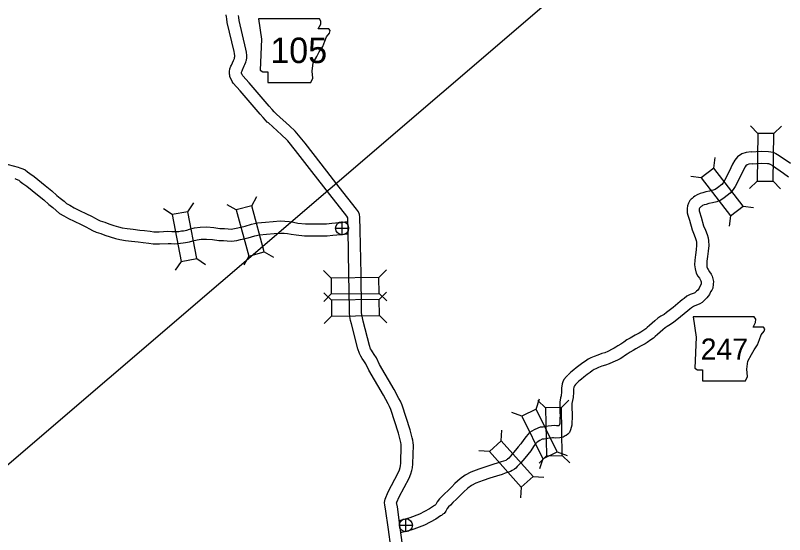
# Model space of a CAD drawing. Extents: x 1374139 to 1377472, y 1168351 to 1170484.
# Drawn here: x 1374736.9 to 1374928.1, y 1170047.2 to 1170176.4 of the extents above; entities that cross this region are included whole.
import ezdxf

# ---------------------------------------------------------------- set-up
doc = ezdxf.new("R2010")
doc.units = 0
doc.layers.add('15', color=7, linetype='Continuous')
doc.layers.add('Default', color=7, linetype='Continuous')

msp = doc.modelspace()

# ---------------------------------------------------------------- linework, layer by layer
at = {"layer": '15'}
msp.add_line((1374910.7, 1170215.21), (1374680.58, 1170017.86), dxfattribs=at)
at = {"layer": 'Default'}
for p, q in [((1374921.48, 1170147.03), (1374919.64, 1170148.92)), ((1374925.44, 1170146.98), (1374927.33, 1170148.82)), ((1374910.54, 1170138.37), (1374910.88, 1170140.99)), ((1374907.4, 1170135.95), (1374904.79, 1170136.3)), ((1374921.32, 1170135.15), (1374919.43, 1170133.31)), ((1374925.28, 1170135.1), (1374927.12, 1170133.2)), ((1374795.65, 1170129.01), (1374796.96, 1170131.3)), ((1374779.81, 1170127.53), (1374781.3, 1170129.71)), ((1374791.83, 1170127.96), (1374789.54, 1170129.27)), ((1374775.92, 1170126.8), (1374773.74, 1170128.29)), ((1374917.79, 1170128.95), (1374920.4, 1170128.61)), ((1374914.65, 1170126.54), (1374914.31, 1170123.92)), ((1374816.51, 1170123.43), (1374819.76, 1170123.43)), ((1374818.13, 1170121.81), (1374818.13, 1170125.06)), ((1374781.99, 1170115.85), (1374784.17, 1170114.36)), ((1374794.97, 1170116.5), (1374793.66, 1170114.21)), ((1374798.79, 1170117.55), (1374801.08, 1170116.24)), ((1374778.1, 1170115.12), (1374776.6, 1170112.95)), ((1374815.4, 1170111.03), (1374813.52, 1170112.88)), ((1374827.28, 1170111.17), (1374829.13, 1170113.06)), ((1374815.47, 1170105.53), (1374813.58, 1170107.37)), ((1374815.45, 1170107.07), (1374813.6, 1170105.18)), ((1374827.33, 1170107.21), (1374829.22, 1170105.36)), ((1374827.35, 1170105.66), (1374829.19, 1170107.55)), ((1374815.51, 1170101.57), (1374813.67, 1170099.68)), ((1374827.39, 1170101.7), (1374829.28, 1170099.86)), ((1374866.36, 1170078.43), (1374867.22, 1170080.93)), ((1374868.71, 1170078.7), (1374866.81, 1170080.53)), ((1374872.67, 1170078.77), (1374874.51, 1170080.67)), ((1374862.8, 1170076.69), (1374860.3, 1170077.55)), ((1374857.67, 1170070.49), (1374857.82, 1170073.13)), ((1374854.73, 1170067.85), (1374852.09, 1170067.99)), ((1374868.92, 1170066.82), (1374867.08, 1170064.92)), ((1374868.02, 1170066.02), (1374867.16, 1170063.52)), ((1374871.58, 1170067.76), (1374874.07, 1170066.9)), ((1374872.87, 1170066.89), (1374874.77, 1170065.05)), ((1374865.6, 1170061.64), (1374868.24, 1170061.5)), ((1374862.66, 1170059), (1374862.51, 1170056.36)), ((1374833.98, 1170047.87), (1374833.98, 1170051.12)), ((1374832.35, 1170049.5), (1374835.6, 1170049.5))]:
    msp.add_line(p, q, dxfattribs=at)
for points in [[(1374789.41, 1170175.95), (1374789.32, 1170176.49)], [(1374830.21, 1170044.11), (1374829.63, 1170048.48), (1374828.9, 1170053.55), (1374828.71, 1170054.49), (1374828.68, 1170055.13), (1374828.8, 1170056.01), (1374829.58, 1170057.85), (1374832.08, 1170062.51), (1374832.4, 1170063.26), (1374832.56, 1170063.84), (1374832.65, 1170064.26), (1374832.72, 1170064.97), (1374832.84, 1170069.37), (1374832.83, 1170069.63), (1374832.75, 1170070.07), (1374832.65, 1170070.47), (1374832.13, 1170072.42), (1374830.22, 1170078.33), (1374829.9, 1170079.08), (1374829.58, 1170079.69), (1374828.42, 1170081.86), (1374824.8, 1170088.07), (1374824.01, 1170089.67), (1374823.56, 1170090.39), (1374823.15, 1170091.02), (1374822.81, 1170091.55), (1374822.45, 1170092.24), (1374822.04, 1170093.38), (1374820.44, 1170099.61), (1374820.23, 1170100.49), (1374820.02, 1170101.48), (1374819.98, 1170102.28), (1374819.93, 1170103.18), (1374819.83, 1170111.98), (1374819.64, 1170122.87), (1374819.56, 1170125.99), (1374819.55, 1170126.04), (1374819.3, 1170126.41), (1374815.06, 1170131.82), (1374810.59, 1170137.58), (1374806.57, 1170142.73), (1374804.63, 1170145.16), (1374804.36, 1170145.46), (1374803.03, 1170146.69), (1374799.81, 1170149.62), (1374799.54, 1170149.85), (1374799.08, 1170150.28), (1374798.51, 1170150.95), (1374797.73, 1170151.82), (1374792.76, 1170157.62), (1374791.08, 1170159.56), (1374790.82, 1170159.96), (1374790.68, 1170160.15), (1374790.39, 1170160.74), (1374790.25, 1170161.18), (1374790.19, 1170161.5), (1374790.15, 1170161.8), (1374790.1, 1170162.43), (1374790.24, 1170163.12), (1374790.48, 1170163.74), (1374790.61, 1170164.04), (1374791.1, 1170165.17), (1374791.26, 1170165.47), (1374791.34, 1170165.66), (1374791.38, 1170165.83), (1374791.4, 1170165.89), (1374791.43, 1170166.12), (1374791.44, 1170166.33), (1374791.38, 1170166.87), (1374791.29, 1170167.42), (1374789.56, 1170174.63), (1374789.46, 1170175.5), (1374789.4, 1170176.02)], [(1374833.17, 1170044.6), (1374832.6, 1170048.89), (1374831.86, 1170054.05), (1374831.7, 1170054.85), (1374831.69, 1170055), (1374831.72, 1170055.22), (1374832.28, 1170056.55), (1374834.79, 1170061.21), (1374835.24, 1170062.27), (1374835.47, 1170063.12), (1374835.62, 1170063.78), (1374835.72, 1170064.78), (1374835.85, 1170069.43), (1374835.81, 1170069.99), (1374835.69, 1170070.69), (1374835.55, 1170071.22), (1374835.01, 1170073.26), (1374833.03, 1170079.39), (1374832.61, 1170080.37), (1374832.23, 1170081.09), (1374831.04, 1170083.32), (1374827.44, 1170089.49), (1374826.64, 1170091.13), (1374826.08, 1170092.01), (1374825.67, 1170092.64), (1374825.42, 1170093.05), (1374825.2, 1170093.45), (1374824.92, 1170094.26), (1374823.35, 1170100.33), (1374823.16, 1170101.15), (1374823, 1170101.87), (1374822.98, 1170102.43), (1374822.93, 1170103.27), (1374822.83, 1170112.02), (1374822.64, 1170122.94), (1374822.55, 1170126.19), (1374822.49, 1170126.81), (1374822.19, 1170127.49), (1374821.71, 1170128.19), (1374817.42, 1170133.66), (1374812.96, 1170139.42), (1374808.93, 1170144.58), (1374806.91, 1170147.12), (1374806.48, 1170147.59), (1374805.06, 1170148.9), (1374801.82, 1170151.84), (1374801.56, 1170152.08), (1374801.25, 1170152.36), (1374800.76, 1170152.93), (1374799.98, 1170153.8), (1374795.03, 1170159.58), (1374793.49, 1170161.36), (1374793.28, 1170161.7), (1374793.24, 1170161.75), (1374793.18, 1170161.87), (1374793.17, 1170161.89), (1374793.16, 1170161.97), (1374793.13, 1170162.13), (1374793.13, 1170162.24), (1374793.13, 1170162.29), (1374793.26, 1170162.62), (1374793.36, 1170162.86), (1374793.81, 1170163.87), (1374793.98, 1170164.19), (1374794.21, 1170164.73), (1374794.28, 1170165.04), (1374794.35, 1170165.28), (1374794.41, 1170165.86), (1374794.45, 1170166.39), (1374794.36, 1170167.27), (1374794.23, 1170168.02), (1374792.52, 1170175.16), (1374792.44, 1170175.85), (1374792.38, 1170176.36)], [(1374919.91, 1170142.44), (1374922.29, 1170142.58), (1374924.11, 1170142.55), (1374924.74, 1170142.47), (1374925.3, 1170142.33), (1374925.94, 1170142.05), (1374926.79, 1170141.53), (1374929.59, 1170139.58)], [(1374919.81, 1170142.44), (1374918.6, 1170142.29), (1374917.5, 1170141.96), (1374916.4, 1170141.18), (1374915.78, 1170140.38), (1374915.22, 1170139.33), (1374914.38, 1170137.53), (1374913.22, 1170135.32), (1374912.88, 1170134.75), (1374912.51, 1170134.28), (1374911.41, 1170133.44), (1374910.88, 1170133.1), (1374910.35, 1170132.89), (1374909.48, 1170132.67), (1374908.57, 1170132.45), (1374907.84, 1170132.26), (1374907.16, 1170132.07), (1374906.39, 1170131.76), (1374905.82, 1170131.41), (1374905.45, 1170131.12), (1374905.17, 1170130.86), (1374904.92, 1170130.63), (1374904.6, 1170130.29), (1374904.26, 1170129.67), (1374904.01, 1170129.02), (1374903.91, 1170128.35), (1374903.89, 1170127.88), (1374903.93, 1170127.24), (1374904.09, 1170126.69), (1374904.46, 1170125.39), (1374905.14, 1170123), (1374905.67, 1170121.8), (1374906.02, 1170120.88), (1374906.16, 1170120.37), (1374906.23, 1170119.96), (1374906.26, 1170119.19), (1374906.15, 1170118.07), (1374905.97, 1170116.77), (1374905.8, 1170115.49), (1374905.77, 1170114.34), (1374905.86, 1170113.28), (1374906.16, 1170112.27), (1374906.56, 1170111.53), (1374906.96, 1170110.98), (1374907.22, 1170110.52), (1374907.32, 1170110.32), (1374907.4, 1170110.07), (1374907.43, 1170109.93), (1374907.42, 1170109.79), (1374907.38, 1170109.48), (1374907.37, 1170109.47), (1374907.06, 1170108.89), (1374906.88, 1170108.5), (1374906.52, 1170108.05), (1374906.23, 1170107.74), (1374906, 1170107.53), (1374905.82, 1170107.37), (1374905.69, 1170107.28), (1374905.36, 1170107.15), (1374904.66, 1170106.9), (1374903.84, 1170106.48), (1374903.14, 1170105.94), (1374902.7, 1170105.58), (1374902.18, 1170105.17), (1374900.39, 1170103.71), (1374899.43, 1170102.98), (1374898.78, 1170102.43), (1374898.15, 1170101.99), (1374897.34, 1170101.52), (1374896.61, 1170101.02), (1374895.87, 1170100.41), (1374895.21, 1170099.82), (1374894.55, 1170099.24), (1374893.98, 1170098.73), (1374893.6, 1170098.41), (1374893.15, 1170098.05), (1374892.41, 1170097.57), (1374891.94, 1170097.3), (1374891.02, 1170096.77), (1374889.72, 1170096.04), (1374888.95, 1170095.61), (1374888.14, 1170095.1), (1374887.39, 1170094.61), (1374886.64, 1170094.14), (1374886.2, 1170093.81), (1374885.79, 1170093.55), (1374885.28, 1170093.31), (1374884.15, 1170092.78), (1374883.45, 1170092.45), (1374882.7, 1170092.23), (1374881.69, 1170091.87), (1374880.76, 1170091.51), (1374879.93, 1170091.15), (1374879.32, 1170090.85), (1374878.62, 1170090.38), (1374878.01, 1170089.96), (1374877.27, 1170089.39), (1374876.32, 1170088.67), (1374875.71, 1170088.17), (1374874.99, 1170087.59), (1374874.29, 1170086.92)], [(1374733.9, 1170139.6), (1374737.64, 1170138.64), (1374738.05, 1170138.49), (1374738.72, 1170138.21), (1374739.35, 1170137.92), (1374739.9, 1170137.48), (1374740.53, 1170137.03), (1374741.54, 1170136.32), (1374744.32, 1170134.05), (1374745.97, 1170132.71), (1374747.18, 1170131.59), (1374748.05, 1170130.91), (1374749.01, 1170130.12), (1374749.65, 1170129.57), (1374750.42, 1170129.13), (1374751.54, 1170128.52), (1374752.88, 1170127.83), (1374754.6, 1170127.02), (1374755.8, 1170126.4), (1374756.72, 1170125.9), (1374757.32, 1170125.58), (1374758.01, 1170125.3), (1374759.13, 1170124.93), (1374760.18, 1170124.53), (1374761.4, 1170124.11), (1374762.58, 1170123.74), (1374763.43, 1170123.54), (1374764.66, 1170123.38), (1374766.17, 1170123.22), (1374767.83, 1170122.98), (1374769.01, 1170122.83), (1374770.43, 1170122.66), (1374771.31, 1170122.56), (1374772.69, 1170122.54), (1374774.82, 1170122.67), (1374775.8, 1170122.64), (1374776.54, 1170122.58), (1374777.18, 1170122.6), (1374777.58, 1170122.64), (1374778.2, 1170122.75), (1374778.73, 1170122.81), (1374779.49, 1170122.95), (1374780.22, 1170123.16), (1374781.45, 1170123.51), (1374782.86, 1170123.69), (1374784.52, 1170123.74), (1374786.2, 1170123.59), (1374787.75, 1170123.39), (1374788.86, 1170123.35), (1374789.77, 1170123.27), (1374790.58, 1170123.21), (1374791.4, 1170123.32), (1374792.17, 1170123.5), (1374794, 1170123.95), (1374795.64, 1170124.4), (1374797.07, 1170124.75), (1374799.07, 1170124.95), (1374801.02, 1170125.12), (1374802.76, 1170125.23), (1374803.9, 1170125.21), (1374804.99, 1170125.13), (1374806.08, 1170124.92), (1374807.13, 1170124.71), (1374808.99, 1170124.5), (1374810.31, 1170124.49), (1374811.38, 1170124.51), (1374812.83, 1170124.5), (1374814.23, 1170124.55), (1374815.56, 1170124.68), (1374816.52, 1170124.75), (1374817.15, 1170124.81), (1374817.9, 1170124.88), (1374818.38, 1170124.94), (1374818.79, 1170124.99), (1374819.3, 1170125.05), (1374819.55, 1170125.06)], [(1374920.17, 1170139.46), (1374919.21, 1170139.34), (1374918.84, 1170139.23), (1374918.5, 1170138.99), (1374918.3, 1170138.73), (1374917.9, 1170137.99), (1374917.08, 1170136.21), (1374915.84, 1170133.84), (1374915.35, 1170133.03), (1374914.63, 1170132.12), (1374913.14, 1170130.98), (1374912.25, 1170130.41), (1374911.27, 1170130.03), (1374910.21, 1170129.76), (1374909.3, 1170129.54), (1374908.61, 1170129.36), (1374908.12, 1170129.22), (1374907.74, 1170129.07), (1374907.55, 1170128.95), (1374907.4, 1170128.83), (1374907.21, 1170128.66), (1374907.04, 1170128.5), (1374906.99, 1170128.41), (1374906.93, 1170128.26), (1374906.9, 1170128.07), (1374906.9, 1170127.91), (1374906.91, 1170127.77), (1374906.98, 1170127.52), (1374907.35, 1170126.2), (1374907.97, 1170124.01), (1374908.44, 1170122.94), (1374908.87, 1170121.83), (1374909.1, 1170121.01), (1374909.22, 1170120.26), (1374909.27, 1170119.11), (1374909.13, 1170117.71), (1374908.94, 1170116.36), (1374908.79, 1170115.25), (1374908.77, 1170114.44), (1374908.82, 1170113.84), (1374908.95, 1170113.42), (1374909.11, 1170113.12), (1374909.49, 1170112.59), (1374909.85, 1170111.96), (1374910.11, 1170111.47), (1374910.31, 1170110.8), (1374910.44, 1170110.19), (1374910.41, 1170109.52), (1374910.26, 1170108.5), (1374910, 1170108.03), (1374909.75, 1170107.56), (1374909.46, 1170106.93), (1374908.8, 1170106.09), (1374908.33, 1170105.59), (1374907.99, 1170105.29), (1374907.64, 1170104.98), (1374907.09, 1170104.61), (1374906.44, 1170104.35), (1374905.85, 1170104.14), (1374905.45, 1170103.93), (1374905.01, 1170103.59), (1374904.58, 1170103.24), (1374904.05, 1170102.83), (1374902.24, 1170101.35), (1374901.31, 1170100.64), (1374900.62, 1170100.05), (1374899.75, 1170099.45), (1374898.94, 1170098.98), (1374898.41, 1170098.62), (1374897.83, 1170098.14), (1374897.21, 1170097.58), (1374896.53, 1170096.99), (1374895.95, 1170096.46), (1374895.5, 1170096.09), (1374894.91, 1170095.61), (1374893.97, 1170095), (1374893.43, 1170094.69), (1374892.51, 1170094.17), (1374891.18, 1170093.42), (1374890.47, 1170093.02), (1374889.76, 1170092.58), (1374889.01, 1170092.09), (1374888.35, 1170091.67), (1374887.92, 1170091.35), (1374887.25, 1170090.91), (1374886.55, 1170090.59), (1374885.42, 1170090.06), (1374884.52, 1170089.64), (1374883.62, 1170089.37), (1374882.73, 1170089.06), (1374881.9, 1170088.73), (1374881.18, 1170088.42), (1374880.82, 1170088.24), (1374880.31, 1170087.91), (1374879.78, 1170087.54), (1374879.08, 1170087), (1374878.18, 1170086.32), (1374877.61, 1170085.84), (1374876.97, 1170085.33), (1374876.37, 1170084.76)], [(1374920.08, 1170139.45), (1374922.35, 1170139.58), (1374923.9, 1170139.56), (1374924.18, 1170139.52), (1374924.32, 1170139.48), (1374924.55, 1170139.38), (1374925.15, 1170139.02), (1374927.83, 1170137.14), (1374929.07, 1170136.23)], [(1374736.75, 1170135.77), (1374736.96, 1170135.69), (1374737.52, 1170135.47), (1374737.76, 1170135.35), (1374738.09, 1170135.09), (1374738.79, 1170134.58), (1374739.73, 1170133.93), (1374742.43, 1170131.72), (1374744, 1170130.45), (1374745.23, 1170129.3), (1374746.18, 1170128.57), (1374747.08, 1170127.83), (1374747.91, 1170127.1), (1374748.96, 1170126.51), (1374750.13, 1170125.87), (1374751.55, 1170125.14), (1374753.27, 1170124.33), (1374754.39, 1170123.74), (1374755.3, 1170123.25), (1374756.05, 1170122.86), (1374756.97, 1170122.48), (1374758.12, 1170122.11), (1374759.16, 1170121.71), (1374760.47, 1170121.26), (1374761.79, 1170120.84), (1374762.89, 1170120.59), (1374764.3, 1170120.4), (1374765.79, 1170120.24), (1374767.43, 1170120.01), (1374768.65, 1170119.85), (1374770.09, 1170119.68), (1374771.13, 1170119.56), (1374772.75, 1170119.54), (1374774.86, 1170119.66), (1374775.65, 1170119.64), (1374776.48, 1170119.58), (1374777.37, 1170119.61), (1374777.99, 1170119.67), (1374778.63, 1170119.78), (1374779.17, 1170119.84), (1374780.18, 1170120.03), (1374781.04, 1170120.27), (1374782.06, 1170120.56), (1374783.1, 1170120.7), (1374784.43, 1170120.74), (1374785.87, 1170120.6), (1374787.51, 1170120.4), (1374788.68, 1170120.36), (1374789.53, 1170120.28), (1374790.66, 1170120.2), (1374791.95, 1170120.37), (1374792.87, 1170120.59), (1374794.75, 1170121.05), (1374796.4, 1170121.5), (1374797.57, 1170121.79), (1374799.35, 1170121.96), (1374801.25, 1170122.13), (1374802.82, 1170122.23), (1374803.76, 1170122.21), (1374804.59, 1170122.15), (1374805.5, 1170121.97), (1374806.67, 1170121.74), (1374808.81, 1170121.5), (1374810.33, 1170121.49), (1374811.4, 1170121.51), (1374812.87, 1170121.5), (1374814.43, 1170121.55), (1374815.83, 1170121.69), (1374816.78, 1170121.77), (1374817.41, 1170121.83), (1374818.23, 1170121.89), (1374818.75, 1170121.96), (1374819.15, 1170122.01), (1374819.56, 1170122.06), (1374819.63, 1170122.07)], [(1374874.25, 1170086.88), (1374873.93, 1170086.55), (1374873.29, 1170085.75), (1374873.04, 1170085.2), (1374872.84, 1170084.68), (1374872.66, 1170083.63), (1374872.64, 1170082.69), (1374872.6, 1170081.75), (1374872.46, 1170081.2), (1374872.27, 1170080.15), (1374872.22, 1170079.46), (1374872.23, 1170078.73), (1374872.24, 1170078.04), (1374872.29, 1170077.46), (1374872.3, 1170076.85), (1374872.29, 1170076.16), (1374872.26, 1170075.39), (1374872.22, 1170074.81), (1374872.17, 1170074.56), (1374872.11, 1170074.35), (1374872, 1170074.28), (1374871.8, 1170074.24), (1374871.45, 1170074.21), (1374870.99, 1170074.3), (1374870.18, 1170074.28), (1374869.35, 1170074.17), (1374868.65, 1170074.07), (1374868.29, 1170073.98), (1374868.02, 1170073.93), (1374867.39, 1170073.88), (1374866.75, 1170073.68), (1374865.84, 1170073.24), (1374864.73, 1170072.55), (1374863.87, 1170071.63), (1374863.28, 1170070.88), (1374862.57, 1170069.8), (1374861.93, 1170068.98), (1374861.26, 1170068.15), (1374860.77, 1170067.58), (1374860.33, 1170067.08), (1374859.95, 1170066.66), (1374859.54, 1170066.2), (1374859.26, 1170065.95), (1374859.16, 1170065.86), (1374859.02, 1170065.77), (1374858.79, 1170065.66), (1374858.27, 1170065.47), (1374857.66, 1170065.27), (1374856.94, 1170065.01), (1374855.63, 1170064.59), (1374853.87, 1170064.05), (1374852.15, 1170063.43), (1374850.15, 1170062.7), (1374848.71, 1170061.96), (1374847.49, 1170061.08), (1374846.19, 1170059.91), (1374845.38, 1170059.07), (1374844.46, 1170058.13), (1374843.61, 1170057.31), (1374842.93, 1170056.66), (1374842.34, 1170056.04), (1374841.73, 1170055.3), (1374841.49, 1170054.82), (1374841.43, 1170054.71), (1374841.27, 1170054.52), (1374841.08, 1170054.43), (1374839.86, 1170053.55), (1374837.36, 1170052.3), (1374834.95, 1170051.33), (1374834.42, 1170051.16), (1374833.55, 1170050.95), (1374832.87, 1170050.76), (1374832.36, 1170050.64)], [(1374876.41, 1170084.8), (1374876.19, 1170084.57), (1374875.87, 1170084.17), (1374875.81, 1170084.04), (1374875.74, 1170083.87), (1374875.65, 1170083.35), (1374875.64, 1170082.59), (1374875.58, 1170081.32), (1374875.4, 1170080.58), (1374875.26, 1170079.78), (1374875.22, 1170079.36), (1374875.23, 1170078.76), (1374875.24, 1170078.2), (1374875.29, 1170077.62), (1374875.3, 1170076.86), (1374875.29, 1170076.08), (1374875.25, 1170075.22), (1374875.2, 1170074.44), (1374875.1, 1170073.85), (1374874.92, 1170073.29), (1374874.62, 1170072.59), (1374874.23, 1170072.18), (1374873.85, 1170071.86), (1374873.58, 1170071.73), (1374873.1, 1170071.45), (1374872.24, 1170071.27), (1374871.3, 1170071.18), (1374870.72, 1170071.29), (1374870.41, 1170071.29), (1374869.77, 1170071.2), (1374869.23, 1170071.12), (1374868.9, 1170071.04), (1374868.39, 1170070.95), (1374867.96, 1170070.92), (1374867.87, 1170070.89), (1374867.29, 1170070.61), (1374866.65, 1170070.21), (1374866.14, 1170069.66), (1374865.71, 1170069.13), (1374865.02, 1170068.06), (1374864.29, 1170067.12), (1374863.57, 1170066.23), (1374863.03, 1170065.6), (1374862.57, 1170065.08), (1374862.18, 1170064.65), (1374861.67, 1170064.09), (1374861.28, 1170063.73), (1374860.95, 1170063.43), (1374860.44, 1170063.13), (1374859.97, 1170062.9), (1374859.26, 1170062.64), (1374858.64, 1170062.43), (1374857.91, 1170062.17), (1374856.53, 1170061.72), (1374854.82, 1170061.2), (1374853.18, 1170060.61), (1374851.35, 1170059.95), (1374850.28, 1170059.4), (1374849.38, 1170058.74), (1374848.27, 1170057.75), (1374847.53, 1170056.98), (1374846.58, 1170056.01), (1374845.69, 1170055.15), (1374845.05, 1170054.53), (1374844.58, 1170054.05), (1374844.27, 1170053.67), (1374844.12, 1170053.37), (1374843.88, 1170052.97), (1374843.46, 1170052.46), (1374843.21, 1170052.23), (1374842.86, 1170051.96), (1374842.63, 1170051.85), (1374841.41, 1170050.98), (1374838.59, 1170049.56), (1374835.96, 1170048.5), (1374835.22, 1170048.27), (1374834.3, 1170048.05), (1374833.61, 1170047.85), (1374832.94, 1170047.69), (1374832.82, 1170047.66)]]:
    msp.add_lwpolyline(points, dxfattribs=at)
for points in [[(1374797.32, 1170175.55), (1374798.08, 1170170.48), (1374797.74, 1170162.78), (1374798.42, 1170162.36), (1374799.69, 1170162.36), (1374799.69, 1170159.65), (1374810.34, 1170159.65), (1374810.85, 1170160.75), (1374810.68, 1170162.52), (1374810.94, 1170164.55), (1374811.87, 1170166.16), (1374812.46, 1170167.35), (1374813.3, 1170168.62), (1374813.81, 1170169.97), (1374814.23, 1170171.07), (1374815, 1170172), (1374815.16, 1170172.59), (1374814.83, 1170173.01), (1374812.2, 1170173.01), (1374812.8, 1170174.2), (1374812.88, 1170174.96), (1374812.53, 1170175.54)], [(1374921.48, 1170147.03), (1374921.32, 1170135.15), (1374925.28, 1170135.1), (1374925.44, 1170146.98)], [(1374917.79, 1170128.95), (1374910.54, 1170138.37), (1374907.4, 1170135.95), (1374914.65, 1170126.54)], [(1374781.99, 1170115.85), (1374779.81, 1170127.53), (1374775.92, 1170126.8), (1374778.1, 1170115.12)], [(1374791.83, 1170127.96), (1374794.97, 1170116.5), (1374798.79, 1170117.55), (1374795.65, 1170129.01)], [(1374815.45, 1170107.07), (1374827.33, 1170107.21), (1374827.28, 1170111.17), (1374815.4, 1170111.03)], [(1374827.35, 1170105.66), (1374815.47, 1170105.53), (1374815.51, 1170101.57), (1374827.39, 1170101.7)], [(1374905.39, 1170101.35), (1374906.15, 1170096.28), (1374905.81, 1170088.58), (1374906.49, 1170088.16), (1374907.76, 1170088.16), (1374907.76, 1170085.45), (1374918.41, 1170085.45), (1374918.92, 1170086.55), (1374918.75, 1170088.33), (1374919.01, 1170090.36), (1374919.94, 1170091.97), (1374920.53, 1170093.15), (1374921.38, 1170094.42), (1374921.88, 1170095.77), (1374922.31, 1170096.87), (1374923.07, 1170097.8), (1374923.24, 1170098.39), (1374922.9, 1170098.82), (1374920.28, 1170098.82), (1374920.87, 1170100), (1374920.95, 1170100.76), (1374920.6, 1170101.35)], [(1374862.8, 1170076.69), (1374868.02, 1170066.02), (1374871.58, 1170067.76), (1374866.36, 1170078.43)], [(1374868.71, 1170078.7), (1374868.92, 1170066.82), (1374872.87, 1170066.89), (1374872.67, 1170078.77)], [(1374854.73, 1170067.85), (1374862.66, 1170059), (1374865.6, 1170061.64), (1374857.67, 1170070.49)]]:
    msp.add_lwpolyline(points, close=True, dxfattribs=at)
for centre in [(1374818.13, 1170123.43), (1374833.98, 1170049.5)]:
    msp.add_circle(centre, 1.62, dxfattribs=at)

# ---------------------------------------------------------------- texts
for s, height, p in [('105', 6.336, (1374800.27, 1170164.53)), ('247', 5.28, (1374907.27, 1170090.7))]:
    msp.add_text(s, height=height, dxfattribs=at).set_placement(p)

doc.saveas('drawing.dxf')
